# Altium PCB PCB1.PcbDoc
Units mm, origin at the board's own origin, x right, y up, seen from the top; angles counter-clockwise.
Board outline 152.4 x 101.6 mm, 2 copper layers (Top Layer, Bottom Layer); 23 components, 18 nets, 93 pads, 63 vias.
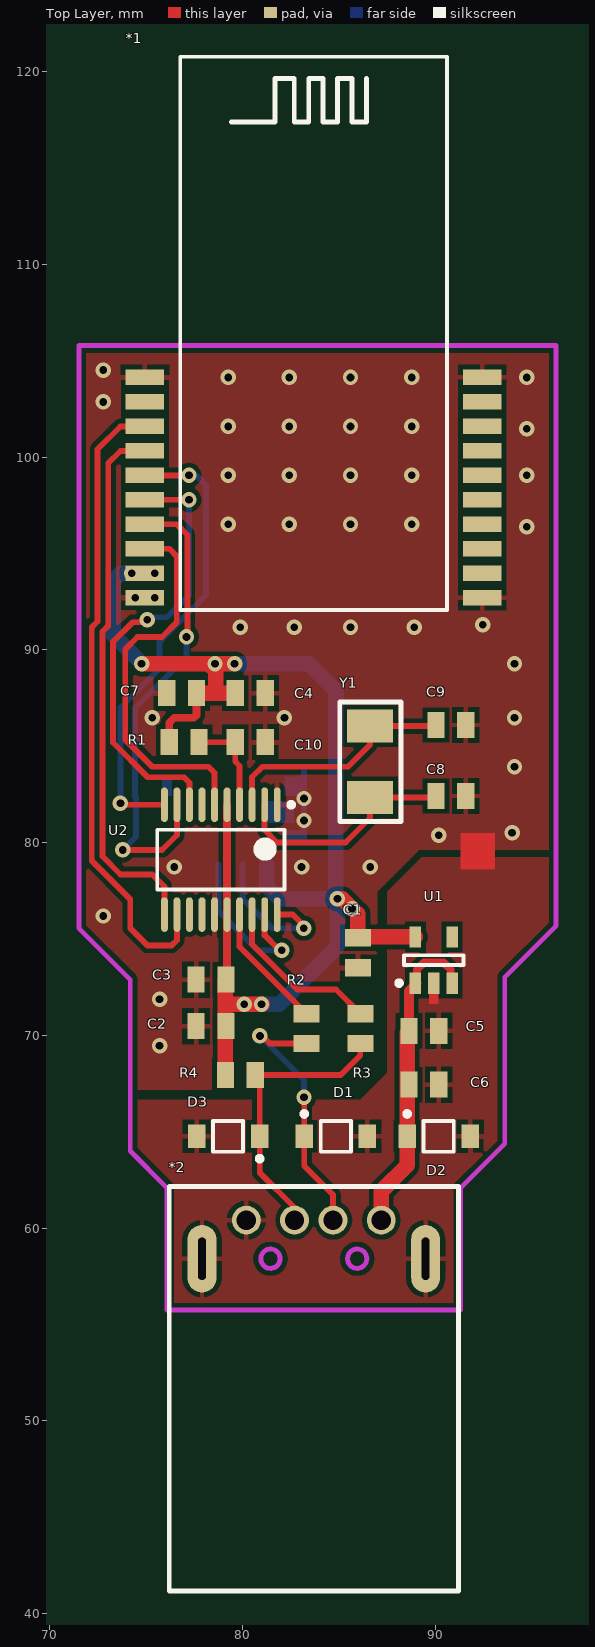
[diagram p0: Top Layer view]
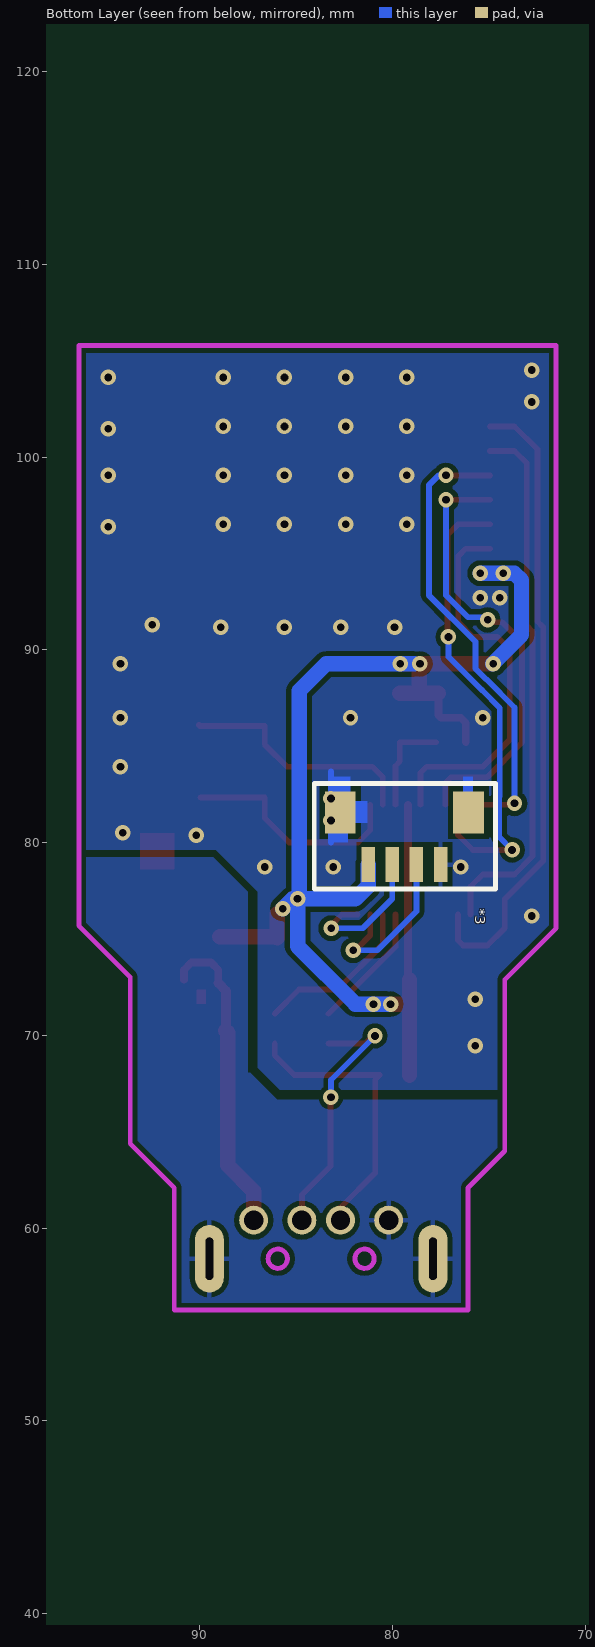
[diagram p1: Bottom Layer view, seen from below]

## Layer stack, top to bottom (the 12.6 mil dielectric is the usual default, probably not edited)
Top Solder: solder mask 0.0102, Solder Resist, Dk 3.5
Top Layer: signal copper 0.0356
Dielectric 1: dielectric 0.32, FR-4, Dk 4.8
Bottom Layer: signal copper 0.0356
Bottom Solder: solder mask 0.0102, Solder Resist, Dk 3.5

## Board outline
25.4,25.4 177.8,25.4 177.8,127 25.4,127

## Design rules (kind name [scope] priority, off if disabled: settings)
Clearance [All] p1: gap=0.254
PolygonConnect [All] p1: connectstyle=Relief reliefconductorwidth=0.254 reliefentries=4 polygonreliefangle="90 Angle" airgapwidth=0.254
RoutingVias [All] p1: holewidth=0.711 width=1.27 viastyle="Through Hole" minholewidth=0.711 minwidth=1.27 maxholewidth=0.711 maxwidth=1.27
SolderMaskExpansion [All] p1: expansion=0.102
Width Width_2 [InNet('Net*2_1')] p1: maxlimit=0.8 minlimit=0.4 preferedwidth=0.8
Width Width_1 [InNet('VCC')] p2: maxlimit=0.8 minlimit=0.4 preferedwidth=0.8
Width [All] p3: maxlimit=0.3 minlimit=0.3 preferedwidth=0.3
29 further rules are at their usual default settings.

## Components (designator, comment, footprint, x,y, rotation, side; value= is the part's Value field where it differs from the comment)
*1 "Wireless" Wireless 74.93,104.14 r0 top
*2 "USB" DIP10 83.693,58.42 r90 top
*3 "Plugin4P" PLUGIN4P 79.375,78.867 r0 bottom
C1 "0.1uf" RESC2013X65X40LL15T20 85.979,74.295 r90 top
C2 "0.1uf" RESC2013X65X40LL15T20 78.359,70.485 r0 top
C3 "10uf" RESC2013X65X40LL15T20 78.359,72.898 r0 top
C4 "10uf" RESC2013X65X40LL15T20 80.391,87.757 r180 top
C5 "10uf" RESC2013X65X40LL15T20 89.408,70.244 r0 top
C6 "10uf" RESC2013X65X40LL15T20 89.408,67.45 r180 top
C7 "10uf" RESC2013X65X40LL15T20 76.835,87.757 r0 top
C8 "22pf" RESC2013X65X40LL15T20 90.805,82.423 r0 top
C9 "22pf" RESC2013X65X40LL15T20 90.805,86.106 r0 top
C10 "0.1uf" RESC2013X65X40LL15T20 80.391,85.217 r180 top
D1 "PTVSHC1DF7VB" ONSC-SOD-123-2-425-04_V 84.836,64.77 r0 top
D2 "PTVSHC1DF7VB" ONSC-SOD-123-2-425-04_V 90.17,64.77 r0 top
D3 "PTVSHC1DF7VB" ONSC-SOD-123-2-425-04_V 79.248,64.77 r180 top
R1 "10k" RESC2013X65X40LL15T20 76.962,85.217 r0 top
R2 "22" RESC2013X65X40LL15T20 83.312,70.358 r90 top
R3 "22" RESC2013X65X40LL15T20 86.106,70.358 r90 top
R4 "1.5k" RESC2013X65X40LL15T20 79.883,67.945 r0 top
U1 "TLV70233DBVR" TI-DBV5_N 89.916,73.914 r90 top
U2 "STM32F070F6P6" STM-TSSOP20_N 78.867,79.121 r270 top
Y1 "8mhz" XTAL 86.614,84.201 r270 top

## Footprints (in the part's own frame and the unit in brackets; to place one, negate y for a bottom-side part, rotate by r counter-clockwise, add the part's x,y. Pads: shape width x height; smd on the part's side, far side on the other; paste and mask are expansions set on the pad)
DIP10 [mm]
  round 1.5 hole 1: 1(2,-3.5) 2(2,-1) 3(2,1) 4(2,3.5)
  oval 3.5x1.5 hole 0.4 slot 2.2 at 0 deg: 4(0,5.8) 4(0,-5.8)
  Keep-Out Layer circle w0.254: c0,2.25 r0.5
  Keep-Out Layer circle w0.254: c0,-2.25 r0.5
  silkscreen extent -17.25,-7.5 3.75,7.5
ONSC-SOD-123-2-425-04_V [mm] "SOD, 2-Leads, Body 2.69x1.6mm"
  rect 0.91x1.22 smd: 1(-1.635,0) 2(1.635,0)
  silkscreen extent -1.76,-0.8 0.78,1.28, body extent -1.35,-0.8 1.35,0.8, height 1.35
PLUGIN4P [mm]
  rect 0.7x1.8 smd: 1(-1.875,0) 2(-0.625,0) 3(0.625,0) 4(1.875,0)
  rect 1.6x2.2 smd: ""(-3.325,-2.7) ""(3.325,-2.7)
  silkscreen extent -4.72,-4.2 4.67,1.28
RESC2013X65X40LL15T20 [mm] "Chip Resistor, 2-Leads, Body 2.00x1.3 mm, IPC High Density"
  rect 0.9x1.35 smd: 1(-0.775,0) 2(0.775,0)
  body extent -1.07,-0.72 1.07,0.72, height 0.65
STM-TSSOP20_N [mm] "SOP, 20-Leads, Body 6.6x4.5mm, Pitch 0.65mm, IPC Medium Density"
  oval 1.8x0.35 smd: 1(-2.85,2.925) 2(-2.85,2.275) 3(-2.85,1.625) 4(-2.85,0.975) 5(-2.85,0.325) 6(-2.85,-0.325) 7(-2.85,-0.975) 8(-2.85,-1.625) 9(-2.85,-2.275) 10(-2.85,-2.925) 11(2.85,-2.925) 12(2.85,-2.275) 13(2.85,-1.625) 14(2.85,-0.975) 15(2.85,-0.325) 16(2.85,0.325) 17(2.85,0.975) 18(2.85,1.625) 19(2.85,2.275) 20(2.85,2.925)
  silkscreen extent -2.97,-3.3 1.55,3.78, body extent -2.25,-3.3 2.25,3.3, height 1.2
TI-DBV5_N [mm] "SOT23, 5-Leads, Body 2.9x1.6mm, Pitch 0.95mm, IPC Medium Density"
  rect 1.1x0.6 smd: 1(-1.2,0.95) 2(-1.2,0) 3(-1.2,-0.95) 4(1.2,-0.95) 5(1.2,0.95)
  silkscreen extent -1.32,-1.55 0.25,1.92, body extent -0.87,-1.52 0.87,1.53, height 1.45
Wireless [mm]
  rect 2x0.8 smd: 1(0,0) 2(0,-1.27) 3(0,-2.54) 4(0,-3.81) 5(0,-5.08) 6(0,-6.35) 7(0,-7.62) 8(0,-8.89) 9(0,-10.16) 10(0,-11.43) 11(17.5,-11.43) 12(17.5,-10.16) 13(17.5,-8.89) 14(17.5,-7.62) 15(17.5,-6.35) 16(17.5,-5.08) 17(17.5,-3.81) 18(17.5,-2.54) 19(17.5,-1.27) 20(17.5,0)
  silkscreen extent 1.84,-12.06 15.67,16.64
XTAL [mm]
  rect 1.7x2.4 smd: 1(-1.85,0) 2(1.85,0)
  silkscreen extent -3.1,-1.58 3.1,1.6

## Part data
C1 C2 C3 C4 C5 C6 C7 C8 C9 C10: library part Cap, "Capacitor"
D1 D2 D3: library part MMSZ39T1G, "Zener Voltage Regulator, 500 mW, 2-Pin SOD-123, Pb-Free, Tape and Reel"
R1 R2 R3 R4: library part Res3, "Resistor"
U1: "Single Output LDO, 300 mA, Fixed 3.3 V Output, 2 to 5.5 V Input, with Low IQ, 5-pin SOT-23 (DBV), -40 to 125 degC, Green (RoHS & no Sb/Br)"
U2: library part STM32F050F6P6, "ARM Cortex-M0 32-bit MCU, 32 KB Flash, 4 KB Internal RAM, 15 I/Os, 20-pin TSSOP, -40 to 85 degC, Tube"
Y1: library part XTAL, "Crystal Oscillator"

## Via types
v1: diameter 0.8, hole 0.4, Top Layer to Bottom Layer, 63 vias

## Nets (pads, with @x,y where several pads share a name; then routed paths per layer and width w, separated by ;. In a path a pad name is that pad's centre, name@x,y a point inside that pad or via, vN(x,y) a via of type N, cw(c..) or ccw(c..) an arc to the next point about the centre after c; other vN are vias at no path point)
GND: *1.1 *1.10 *1.11 *1.20 *2.4 *3. *3.1 C1.1 C2.1 C3.1 C4.1 C5.2 C6.1 C7.1 C8.2 C9.2 C10.1 D1.2 D2.2 D3.2 U1.2 U2.1 U2.15 | length 3.7
  Bottom Layer w0.3: 83.185,80.01 v1(83.185,81.153) 83.185,83.693
  other v1: 75.692,69.469 75.692,71.882 72.771,76.2 76.454,78.74 83.058,78.74 86.614,78.74 90.17,80.391 93.98,80.518 83.185,82.296 94.107,83.947 75.311,86.487 82.169,86.487 94.107,86.487 94.107,89.281 79.883,91.186 82.677,91.186 85.598,91.186 88.9,91.186 92.456,91.313 74.422,92.71 75.438,92.71 94.742,96.393 79.248,96.52 82.423,96.52 85.598,96.52 88.773,96.52 79.248,99.06 82.423,99.06 85.598,99.06 88.773,99.06 94.742,99.06 94.742,101.473 79.248,101.6 82.423,101.6 85.598,101.6 88.773,101.6 72.771,102.87 79.248,104.14 82.423,104.14 85.598,104.14 88.773,104.14 94.742,104.14 72.771,104.521
Net*1_3: *1.3 U2.12 | length 33
  Top Layer w0.3: *1.3 73.66,101.6 72.471,100.411 72.471,91.483 72.171,91.183 72.171,79.065 74.168,77.068 74.168,75.565 75.057,74.676 76.327,74.676 76.592,74.941 U2.12
Net*1_4: *1.4 U2.11 | length 28
  Top Layer w0.3: *1.4 73.66,100.33 73.025,99.695 73.025,91.253 72.725,90.953 72.725,79.294 73.66,78.359 75.311,78.359 75.942,77.728 U2.11
Net*1_5: *1.5 U2.10 | length 24.1
  Top Layer w0.3: v1(73.66,82.042) 73.731,81.971 U2.10 ; *1.5 v1(77.216,99.06)
  Bottom Layer w0.3: v1(73.66,82.042) 73.66,87.016 75.121,88.477 75.136,88.477 75.692,89.033 75.692,90.424 78.105,92.837 78.105,98.552 77.597,99.06 v1(77.216,99.06)
Net*1_6: *1.6 U2.8 | length 23.5
  Top Layer w0.3: *1.6 v1(77.216,97.79) ; v1@75.057,91.694 75.057,91.44 74.295,91.44 73.279,90.424 73.279,85.196 75.082,83.393 76.962,83.393 77.242,83.113 U2.8
  Bottom Layer w0.3: v1@75.057,91.694 76.073,91.694 77.216,92.837 v1(77.216,97.79)
  other v1: 75.057,91.567
Net*1_7: *1.7 U2.9 | length 24.9
  Top Layer w0.3: v1(73.787,79.629) 75.819,79.629 76.592,80.402 U2.9 ; *1.7 76.581,96.52 77.135,95.966 v1@77.135,90.678
  Bottom Layer w0.3: v1(73.787,79.629) 74.464,80.306 74.464,82.375 74.422,82.417 74.422,86.995 75.35,87.923 75.366,87.923 77.089,89.647 v1(77.089,90.678)
Net*1_8: *1.8 U2.6 | length 20.2
  Top Layer w0.3: *1.8 76.2,95.25 76.581,94.869 76.581,91.44 75.819,90.678 74.549,90.678 73.914,90.043 73.914,85.344 75.311,83.947 78.232,83.947 78.542,83.637 U2.6
Net*2_1: *2.1 C5.1 C6.2 D2.1 U1.1 U1.3 | length 16.3
  Top Layer w0.4: U1.1@89.027,72.714 89.027,73.406 89.408,73.787 90.424,73.787 90.805,73.406 U1.3@90.805,72.898
  Top Layer w0.5: C5.1 88.633,72.32 U1.1@89.027,72.714
  Top Layer w0.8: *2.1 87.193,61.92 88.535,63.262 D2.1 88.535,70.146 C5.1
Net*2_2: *2.2 D1.1 R2.1 | length 13.7
  Top Layer w0.3: v1(80.899,69.977) 81.026,69.977 81.42,69.583 R2.1 ; v1(83.185,66.802) 83.201,66.786 D1.1 83.201,63.23 84.693,61.738 *2.2
  Bottom Layer w0.3: v1(80.899,69.977) 83.185,67.691 v1(83.185,66.802)
Net*2_3: *2.3 D3.1 R3.1 R4.2 | length 14.9
  Top Layer w0.3: *2.3 82.693,61.071 80.883,62.881 D3.1 80.883,67.72 R4.2 85.09,67.945 86.106,68.961 R3.1
Net*3_2: *3.2 U2.19 | length 8.8
  Top Layer w0.3: U2.19 81.142,75.195 81.788,74.549 v1@81.788,74.295
  Bottom Layer w0.3: *3.2 78.75,76.444 80.772,74.422 v1(82.026,74.422)
Net*3_3: *3.3 U2.20 | length 7.2
  Top Layer w0.3: U2.20 82.606,76.271 v1@83.185,75.692
  Bottom Layer w0.3: *3.3 80,77.099 81.534,75.565 v1(83.169,75.565)
NetC8_1: C8.1 U2.2 Y1.2 | length 12
  Top Layer w0.3: U2.2 81.142,80.656 81.788,80.01 85.344,80.01 86.614,81.28 Y1.2 C8.1@89.958,82.351
NetC9_1: C9.1 U2.3 Y1.1 | length 12.7
  Top Layer w0.3: U2.3 80.492,83.413 81.026,83.947 85.471,83.947 86.614,85.09 Y1.1 89.975,86.051 C9.1
NetC10_2: C10.2 R1.2 U2.4 | length 5.2
  Top Layer w0.3: R1.2 C10.2 79.616,84.214 79.842,83.988 U2.4
NetR2_2: R2.2 U2.17 | length 6.6
  Top Layer w0.3: U2.17 79.842,74.603 R2.2
NetR3_2: R3.2 U2.18 | length 8.6
  Top Layer w0.3: U2.18 80.492,74.736 82.838,72.39 84.849,72.39 R3.2
VCC: *1.9 *3.4 C1.2 C2.2 C3.2 C4.2 C7.2 R1.1 R4.1 U1.5 U2.5 U2.16 | length 72.3
  Top Layer w0.4: R1.1 76.187,86.22 76.454,86.487 77.47,86.487 77.61,86.627 C7.2 ; C3.2@79.108,72.898 79.192,72.982 U2.5
  Top Layer w0.8: v1@74.803,89.281 v1@78.232,89.281 ; C7.2 78.567,87.757 ; R4.1 79.108,71.628 ; C3.2@79.108,72.898 79.108,71.628 ; v1(79.583,89.281) v1@78.232,89.281 ; C4.2 78.567,87.757 ; v1@81.026,71.628 v1(80.98,71.628) v1(80.091,71.628) 79.108,71.628 ; v1(84.917,77.089) 85.171,77.089 v1(85.679,76.581) ; v1@85.979,76.327 C1.2 86.023,75.114 U1.5 ; v1@78.232,89.281 78.613,88.9 78.613,87.803 78.567,87.757
  Bottom Layer w0.8: v1@74.803,89.281 73.298,90.786 73.298,93.618 73.66,93.98 v1(75.438,93.98) ; v1@78.867,89.281 83.439,89.281 84.836,87.884 84.836,77.089 81.915,77.089 81.25,77.754 *3.4 ; v1@80.264,71.628 81.915,71.628 84.917,74.63 v1(84.917,77.089) 85.171,77.089 v1(85.679,76.581)
  other v1: 74.757,89.281 78.567,89.281 74.249,93.98
pads on no net: *1.2 *1.12 *1.13 *1.14 *1.15 *1.16 *1.17 *1.18 *1.19 U1.4 U2.7 U2.13 U2.14

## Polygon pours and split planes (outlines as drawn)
GND on Top Layer "Bottom Layer-No Net" (solid, remove dead copper, pour order 8): 96.266,79.629 89.281,79.629 89.154,79.629 86.995,77.47 86.995,68.199 86.995,68.072 86.106,67.183 74.168,67.183 74.168,72.898 71.501,75.565 71.501,105.791 96.266,105.791 96.266,79.629
GND on Top Layer "Bottom Layer-No Net" (solid, remove dead copper, pour order 4): 76.073,55.753 91.313,55.753 91.313,62.103 93.599,64.389 93.599,73.025 96.266,75.692 96.266,79.248 89.281,79.248 87.503,77.47 87.503,68.072 86.106,66.675 74.168,66.675 74.168,64.008 76.073,62.103 76.073,55.753
GND on Bottom Layer "Bottom Layer-No Net" (solid, remove dead copper, pour order 10): 96.266,79.629 89.154,79.629 86.995,77.47 86.995,68.453 86.995,68.326 85.852,67.183 74.168,67.183 74.168,72.898 71.501,75.565 71.501,105.791 96.266,105.791
GND on Bottom Layer "Bottom Layer-No Net" (solid, remove dead copper, pour order 6): 76.073,55.753 91.313,55.753 91.313,62.103 93.599,64.389 93.599,73.025 96.266,75.692 96.266,79.248 89.281,79.248 87.503,77.47 87.503,68.072 87.376,68.072 85.979,66.675 74.168,66.675 74.168,64.008 76.073,62.103 76.073,55.753

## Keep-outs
Keep-Out Layer:
  lines w0.254: 71.501,75.565 71.501,98.298 71.501,105.791 96.266,105.791 96.266,75.692 93.599,73.025 93.599,64.389 91.313,62.103 91.313,55.753 76.073,55.753 76.073,62.103 74.168,64.008 74.168,72.898 71.501,75.565

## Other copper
Top Layer:
  rectangle net GND: 89.662,71.628 90.17,72.39
  rectangle net GND: 91.313,78.613 93.091,80.518
Bottom Layer:
  rectangle net GND: 75.819,82.423 76.327,83.439
  rectangle net GND: 82.296,80.01 83.185,80.645
  rectangle net GND: 82.169,82.423 83.185,83.439
  rectangle net GND: 81.28,81.026 82.677,82.169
